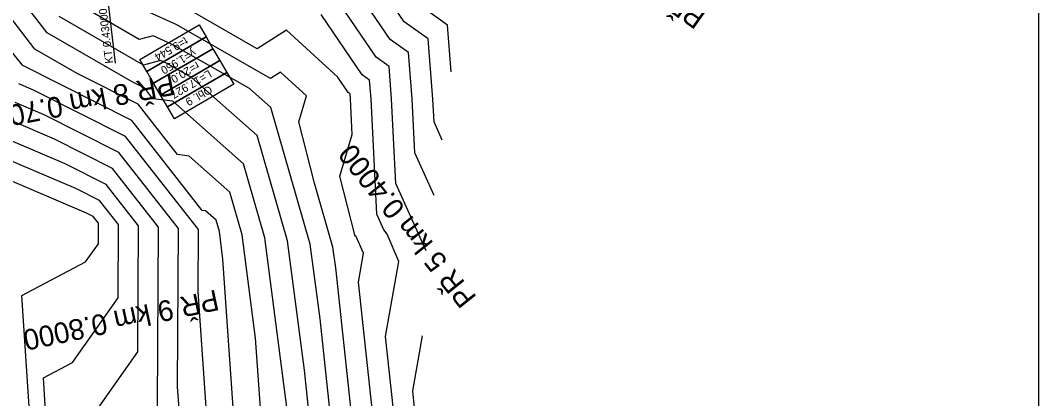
# Model space of a CAD drawing. Extents: x -549394 to -546608, y -1037055 to -1033629.
# Drawn here: x -547053.3 to -546608, y -1036262.8 to -1036097.5 of the extents above; entities that cross this region are included whole.
import ezdxf

# ---------------------------------------------------------------- set-up
doc = ezdxf.new("R2010")
doc.units = 0
for name, color, linetype in [('hlavni_vrst', 7, 'Continuous'), ('norm_vrst', 7, 'Continuous'), ('ram', 7, 'Continuous'), ('x_popis_oblouky_C31', 7, 'Continuous'), ('x_popis_pricne_rezy_C31', 7, 'Continuous')]:
    doc.layers.add(name, color=color, linetype=linetype)

msp = doc.modelspace()

# ---------------------------------------------------------------- linework, layer by layer
at = {"layer": 'hlavni_vrst'}
for p, q in [((-547046.99, -1036110.07), (-547059.82, -1036093.31)), ((-546949.68, -1036109.91), (-546982.69, -1036091.05)), ((-546866.48, -1036099.58), (-546879.4, -1036090.41)), ((-546936.86, -1036101.81), (-546949.68, -1036109.91)), ((-546914.52, -1036122.41), (-546936.86, -1036101.81)), ((-546864.85, -1036120), (-546866.48, -1036099.58)), ((-547028.5, -1036120.77), (-547046.99, -1036110.07)), ((-547001.74, -1036134.23), (-547028.5, -1036120.77)), ((-546909.96, -1036129.13), (-546914.52, -1036122.41)), ((-546909.14, -1036129.71), (-546909.96, -1036129.13)), ((-546908.97, -1036131.77), (-546909.14, -1036129.71)), ((-546908.19, -1036147.44), (-546908.97, -1036131.77)), ((-546984.56, -1036156.16), (-547001.74, -1036134.23)), ((-546913.59, -1036165.62), (-546908.19, -1036147.44)), ((-547033.64, -1036160.27), (-547058.66, -1036149.61)), ((-546979.52, -1036156.84), (-546984.56, -1036156.16)), ((-547015.8, -1036169.24), (-547033.64, -1036160.27)), ((-546961.72, -1036172.58), (-546979.52, -1036156.84)), ((-547001.64, -1036187.32), (-547015.8, -1036169.24)), ((-546906.83, -1036191.79), (-546913.59, -1036165.62)), ((-546956.33, -1036191.2), (-546961.72, -1036172.58)), ((-547001.91, -1036242.41), (-547001.64, -1036187.32)), ((-546950.44, -1036236.45), (-546956.33, -1036191.2)), ((-546906.55, -1036191.64), (-546906.83, -1036191.79)), ((-546903.24, -1036199.32), (-546906.55, -1036191.64)), ((-546905.45, -1036211.88), (-546903.24, -1036199.32)), ((-546899.28, -1036268.6), (-546905.45, -1036211.88)), ((-546947.86, -1036273.47), (-546950.44, -1036236.45)), ((-547030.9, -1036283.3), (-547001.91, -1036242.41))]:
    msp.add_line(p, q, dxfattribs=at)
at = {"layer": 'norm_vrst'}
for p, q in [((-546891.63, -1036105.9), (-546920.09, -1036063.93)), ((-546897.74, -1036113.64), (-546929.09, -1036067.41)), ((-546885.51, -1036098.16), (-546905.93, -1036068.05)), ((-547041.62, -1036102.95), (-547064.74, -1036072.76)), ((-547052.42, -1036117.11), (-547079.46, -1036083.53)), ((-547001.28, -1036105.84), (-547030.88, -1036088.71)), ((-546984.92, -1036099.46), (-546998.41, -1036093.4)), ((-546999.51, -1036117.09), (-547036.25, -1036095.83)), ((-546903.85, -1036121.38), (-546921.8, -1036094.91)), ((-546875.01, -1036105.61), (-546885.51, -1036098.16)), ((-547004.45, -1036124.45), (-547041.62, -1036102.95)), ((-546943.93, -1036122.88), (-546984.92, -1036099.46)), ((-546995.18, -1036104.27), (-547001.28, -1036105.84)), ((-546987.15, -1036107.88), (-546995.18, -1036104.27)), ((-546883.54, -1036111.63), (-546891.63, -1036105.9)), ((-546872.91, -1036131.94), (-546875.01, -1036105.61)), ((-546953.12, -1036127.32), (-546987.15, -1036107.88)), ((-546881.93, -1036131.9), (-546883.54, -1036111.63)), ((-546991.94, -1036115.14), (-546999.51, -1036117.09)), ((-546989.37, -1036116.29), (-546991.94, -1036115.14)), ((-546978.49, -1036122.51), (-546989.37, -1036116.29)), ((-546892.08, -1036117.66), (-546897.74, -1036113.64)), ((-547052.38, -1036117.18), (-547052.42, -1036117.11)), ((-547052.32, -1036117.2), (-547052.38, -1036117.18)), ((-547052.25, -1036117.23), (-547052.32, -1036117.2)), ((-547004.55, -1036141.24), (-547052.25, -1036117.23)), ((-546939.54, -1036120.11), (-546943.93, -1036122.88)), ((-546928.2, -1036130.57), (-546939.54, -1036120.11)), ((-546890.94, -1036131.86), (-546892.08, -1036117.66)), ((-546998.93, -1036127.23), (-547004.45, -1036124.45)), ((-546949.78, -1036147.89), (-546978.49, -1036122.51)), ((-546900.61, -1036123.69), (-546903.85, -1036121.38)), ((-546899.96, -1036131.82), (-546900.61, -1036123.69)), ((-547047.6, -1036127.99), (-547053.9, -1036125.3)), ((-547007.37, -1036148.24), (-547047.6, -1036127.99)), ((-546995.39, -1036131.76), (-546998.93, -1036127.23)), ((-546943.81, -1036135.55), (-546953.12, -1036127.32)), ((-547042.95, -1036138.75), (-547055.49, -1036133.41)), ((-546986.65, -1036132.92), (-546995.39, -1036131.76)), ((-546955.75, -1036160.24), (-546986.65, -1036132.92)), ((-546931.58, -1036141.94), (-546928.2, -1036130.57)), ((-546897.43, -1036182.25), (-546899.96, -1036131.82)), ((-546889.09, -1036168.8), (-546890.94, -1036131.86)), ((-546880.75, -1036155.36), (-546881.93, -1036131.9)), ((-546872.41, -1036141.92), (-546872.91, -1036131.94)), ((-546926.52, -1036195.27), (-546943.81, -1036135.55)), ((-547038.29, -1036149.51), (-547057.08, -1036141.51)), ((-547010.18, -1036155.24), (-547042.95, -1036138.75)), ((-546973.74, -1036180.57), (-547004.55, -1036141.24)), ((-546924.69, -1036168.64), (-546931.58, -1036141.94)), ((-546868.83, -1036149.89), (-546872.41, -1036141.92)), ((-547012.99, -1036162.24), (-547038.29, -1036149.51)), ((-546975.43, -1036189), (-547007.37, -1036148.24)), ((-546936.46, -1036193.91), (-546949.78, -1036147.89)), ((-546984.17, -1036188.44), (-547010.18, -1036155.24)), ((-546872.34, -1036174.1), (-546880.75, -1036155.36)), ((-547028.99, -1036171.02), (-547060.25, -1036157.72)), ((-546946.39, -1036192.56), (-546955.75, -1036160.24)), ((-546992.9, -1036187.88), (-547012.99, -1036162.24)), ((-547024.33, -1036181.78), (-547061.84, -1036165.82)), ((-546916.59, -1036196.62), (-546924.69, -1036168.64)), ((-546875.84, -1036198.32), (-546889.09, -1036168.8)), ((-547018.61, -1036176.25), (-547028.99, -1036171.02)), ((-547010.38, -1036186.76), (-547018.61, -1036176.25)), ((-547021.42, -1036183.25), (-547024.33, -1036181.78)), ((-546972.4, -1036180.75), (-546973.74, -1036180.57)), ((-546967.69, -1036184.92), (-546972.4, -1036180.75)), ((-546894.33, -1036189.14), (-546897.43, -1036182.25)), ((-547019.11, -1036186.2), (-547021.42, -1036183.25)), ((-547019.16, -1036195.19), (-547019.11, -1036186.2)), ((-547010.53, -1036218.8), (-547010.38, -1036186.76)), ((-546966.26, -1036189.85), (-546967.69, -1036184.92)), ((-546993.29, -1036266.03), (-546992.9, -1036187.88)), ((-546984.51, -1036257.66), (-546984.17, -1036188.44)), ((-546975.56, -1036216.01), (-546975.43, -1036189)), ((-546964.71, -1036201.82), (-546966.26, -1036189.85)), ((-546892.94, -1036190.93), (-546894.33, -1036189.14)), ((-546887.81, -1036202.84), (-546892.94, -1036190.93)), ((-547024.76, -1036203.1), (-547019.16, -1036195.19)), ((-546936.18, -1036271.07), (-546946.39, -1036192.56)), ((-546929.11, -1036250.4), (-546936.46, -1036193.91)), ((-546922.26, -1036228.02), (-546926.52, -1036195.27)), ((-546915.41, -1036205.64), (-546916.59, -1036196.62)), ((-547052.63, -1036217.76), (-547024.76, -1036203.1)), ((-546959.62, -1036274.79), (-546964.71, -1036201.82)), ((-546893.58, -1036235.66), (-546887.81, -1036202.84)), ((-546908.47, -1036269.49), (-546915.41, -1036205.64)), ((-547048.21, -1036285.17), (-547052.63, -1036217.76)), ((-546971.37, -1036276.11), (-546975.56, -1036216.01)), ((-547030.52, -1036246.98), (-547010.53, -1036218.8)), ((-546917.65, -1036270.37), (-546922.26, -1036228.02)), ((-546890.09, -1036267.72), (-546893.58, -1036235.66)), ((-546881.71, -1036259.44), (-546877.49, -1036235.44)), ((-547043.24, -1036253.68), (-547030.52, -1036246.98)), ((-547041.22, -1036284.45), (-547043.24, -1036253.68)), ((-546926.84, -1036271.25), (-546929.11, -1036250.4)), ((-546983.13, -1036277.42), (-546984.51, -1036257.66)), ((-546880.91, -1036266.84), (-546881.71, -1036259.44))]:
    msp.add_line(p, q, dxfattribs=at)
at = {"layer": 'ram'}
msp.add_lwpolyline([(-549394.28, -1037054.81), (-549394.28, -1033629.11), (-546608.04, -1033629.11), (-546608.04, -1037054.81), (-549394.28, -1037054.81)], dxfattribs=at)
at = {"layer": 'x_popis_oblouky_C31'}
msp.add_lwpolyline([(-547011.62, -1036116.25), (-547016.53, -1036075.17)], dxfattribs=at)
for points in [[(-546972.11, -1036104.72), (-546998.02, -1036119.84), (-547001.04, -1036114.66), (-546975.13, -1036099.54)], [(-546969.08, -1036109.91), (-546995, -1036125.02), (-546998.02, -1036119.84), (-546972.11, -1036104.72)], [(-546966.06, -1036115.09), (-546991.97, -1036130.2), (-546995, -1036125.02), (-546969.08, -1036109.91)], [(-546963.04, -1036120.27), (-546988.95, -1036135.39), (-546991.97, -1036130.2), (-546966.06, -1036115.09)], [(-546960.01, -1036125.45), (-546985.93, -1036140.57), (-546988.95, -1036135.39), (-546963.04, -1036120.27)]]:
    msp.add_lwpolyline(points, close=True, dxfattribs=at)

# ---------------------------------------------------------------- texts
for s, rotation, p in [('KT 0.43000', 96.8135, (-547012.69, -1036116.19)), ('t=9.544', 210.2783, (-546981.39, -1036104.59)), ('y=1.950', 210.2783, (-546977.79, -1036109.84)), ('r=20.0', 210.2783, (-546976.3, -1036115.41)), ('L=17.927', 210.2783, (-546970.94, -1036119.03)), ('Obl. 9', 210.2783, (-546970.69, -1036125.83))]:
    msp.add_text(s, height=3.5, rotation=rotation, dxfattribs=at).set_placement(p)
at = {"layer": 'x_popis_pricne_rezy_C31'}
for s, rotation, p in [('PŘ 4 km 0.3000', 144.501, (-546752.87, -1036094.5)), ('PŘ 8 km 0.7000', 190.8879, (-546986.85, -1036121.03)), ('PŘ 5 km 0.4000', 128.7208, (-546853.47, -1036218.5)), ('PŘ 9 km 0.8000', 191.9326, (-546967.67, -1036215.11))]:
    msp.add_text(s, height=9.0627, rotation=rotation, dxfattribs=at).set_placement(p)

doc.saveas('drawing.dxf')
